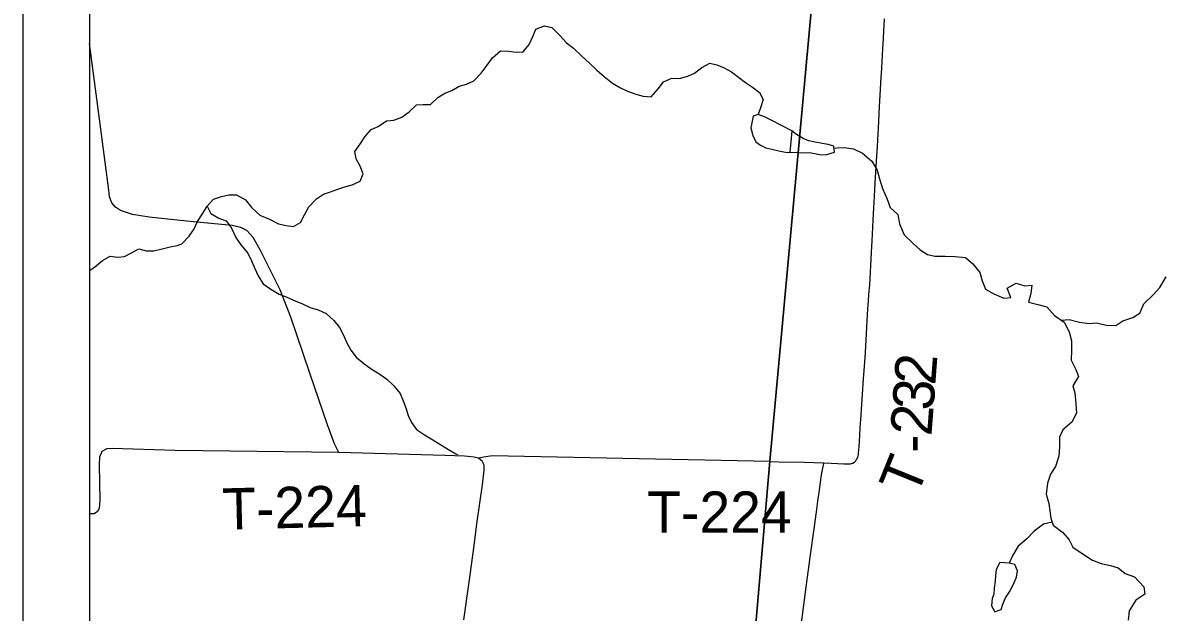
# Model space of a CAD drawing. Extents: x 0 to 34, y 0 to 22.
# Drawn here: x 2.17 to 3.738, y 15.952 to 16.763 of the extents above; entities that cross this region are included whole.
import ezdxf

# ---------------------------------------------------------------- set-up
doc = ezdxf.new("R2010")
doc.units = 0
for name, color, linetype in [('Default', 7, 'Continuous'), ('GM_X_County_Road', 7, 'Continuous'), ('GM_X_Minor_Lake', 7, 'Continuous'), ('GM_X_Minor_River', 7, 'Continuous'), ('GM_X_Township_Road', 7, 'Continuous'), ('GM_X_Township_Road_Text', 7, 'Continuous'), ('SH_Cut_Line', 7, 'Continuous'), ('SH_Data', 7, 'Continuous')]:
    doc.layers.add(name, color=color, linetype=linetype)

msp = doc.modelspace()

# ---------------------------------------------------------------- linework, layer by layer
at = {"layer": 'Default'}
for points in [[(2.2621, 19.2337), (2.2621, 13.6252), (2.9696, 13.6252), (3.0429, 14.4692), (3.0457, 14.4958), (3.0617, 14.6751), (3.1343, 15.4291), (3.1974, 16.1596), (3.2667, 16.919), (3.2768, 17.1355), (3.47, 19.2407)], [(3.47, 19.2407), (3.2768, 17.1355), (3.2667, 16.919), (3.1974, 16.1596), (3.1343, 15.4291), (3.1796, 15.4266), (4.2078, 15.3826), (4.2393, 15.3805), (4.819, 15.349), (5.5157, 15.319), (7.9465, 15.1727), (8.1234, 15.1688), (8.137, 15.3372), (8.146, 15.4642), (8.2031, 16.209), (8.2895, 16.85), (8.3286, 17.3076), (8.3307, 17.3314), (8.3334, 17.361), (8.3935, 18.0719)]]:
    msp.add_lwpolyline(points, dxfattribs=at)
at = {"layer": 'GM_X_County_Road'}
for points in [[(2.6049, 16.1715), (2.5987, 16.1832), (2.5893, 16.2095), (2.5651, 16.2807), (2.5388, 16.3579), (2.5242, 16.3953), (2.4965, 16.4504), (2.4872, 16.4673), (2.4785, 16.477), (2.47, 16.481), (2.4584, 16.4836), (2.3954, 16.4896), (2.3441, 16.4954), (2.3214, 16.4988), (2.3047, 16.5043), (2.2976, 16.509), (2.2928, 16.515), (2.2898, 16.5232), (2.2885, 16.5326), (2.2786, 16.6093), (2.268, 16.6892), (2.2621, 16.7341)], [(2.7969, 16.1635), (2.7907, 16.1653), (2.7774, 16.1665), (2.7506, 16.1673), (2.6049, 16.1715)], [(2.7767, 15.9414), (2.7837, 15.9931), (2.7897, 16.0368), (2.795, 16.0765), (2.8022, 16.1271), (2.8046, 16.1471), (2.8044, 16.1542), (2.8017, 16.1598), (2.7969, 16.1635)]]:
    msp.add_lwpolyline(points, dxfattribs=at)
at = {"layer": 'GM_X_Minor_Lake'}
msp.add_line((3.2275, 16.614), (3.2247, 16.5843), dxfattribs=at)
for points in [[(3.2275, 16.614), (3.199, 16.6287), (3.19, 16.6334), (3.181, 16.6366), (3.1745, 16.6341), (3.1711, 16.6182), (3.1739, 16.6076), (3.1779, 16.5991), (3.1842, 16.5941), (3.1918, 16.5905), (3.2001, 16.5888), (3.2095, 16.5863), (3.2185, 16.5846), (3.2247, 16.5843)], [(3.2247, 16.5843), (3.2318, 16.5848), (3.2424, 16.5838), (3.2519, 16.5844), (3.2677, 16.581), (3.2757, 16.5816), (3.286, 16.5848), (3.285, 16.5928), (3.2775, 16.5952), (3.2692, 16.5965), (3.2593, 16.5983), (3.251, 16.6003), (3.2432, 16.6035), (3.2339, 16.6091), (3.2275, 16.614)], [(3.5263, 16.0194), (3.5134, 16.02), (3.5083, 16.0106), (3.5074, 16.0016), (3.5068, 15.9951), (3.5055, 15.9849), (3.505, 15.9766), (3.5029, 15.9705), (3.502, 15.9607), (3.5063, 15.9523), (3.511, 15.954)], [(3.511, 15.954), (3.5151, 15.9555), (3.5176, 15.963), (3.5211, 15.9717), (3.5266, 15.9799), (3.5321, 15.9904), (3.5361, 16.0002), (3.5374, 16.0089), (3.5338, 16.0173), (3.5263, 16.0194)]]:
    msp.add_lwpolyline(points, dxfattribs=at)
at = {"layer": 'GM_X_Minor_River'}
for points in [[(2.3892, 16.4587), (2.3993, 16.4691), (2.406, 16.4792), (2.4107, 16.4893), (2.4174, 16.4998), (2.4237, 16.5103), (2.4326, 16.52), (2.4433, 16.5239), (2.4536, 16.526), (2.4642, 16.5261), (2.4765, 16.5191), (2.4854, 16.5083), (2.4962, 16.4982), (2.5093, 16.4926), (2.5217, 16.4863), (2.5326, 16.4838), (2.5424, 16.4824), (2.552, 16.4879), (2.5576, 16.4984), (2.5635, 16.5097), (2.5739, 16.5205), (2.5839, 16.5267), (2.5934, 16.5303), (2.6034, 16.5339), (2.6129, 16.5368), (2.6232, 16.5396), (2.6339, 16.545), (2.6383, 16.5548), (2.6339, 16.5655), (2.6285, 16.5755), (2.6268, 16.5854), (2.6338, 16.5951), (2.6405, 16.6056), (2.6494, 16.6157), (2.6589, 16.62), (2.6701, 16.6278), (2.6803, 16.6287), (2.6914, 16.633), (2.7014, 16.64), (2.7114, 16.6497), (2.7209, 16.6502), (2.7308, 16.6504), (2.7408, 16.6597), (2.7504, 16.6659), (2.7603, 16.6695), (2.7703, 16.6754), (2.7802, 16.6782), (2.7902, 16.683), (2.8006, 16.6934), (2.8088, 16.7046), (2.8162, 16.7143), (2.827, 16.7239), (2.838, 16.7237), (2.8486, 16.7223), (2.858, 16.7225), (2.8666, 16.733), (2.8714, 16.7439), (2.8757, 16.754), (2.8876, 16.7583), (2.8974, 16.7562), (2.9085, 16.7454), (2.9178, 16.7353), (2.9275, 16.7276), (2.939, 16.7167), (2.9494, 16.707), (2.9594, 16.6973), (2.9695, 16.6888), (2.9811, 16.6798), (2.9919, 16.6731), (3.0017, 16.6688), (3.0129, 16.6647), (3.0231, 16.6619), (3.0341, 16.6609), (3.0438, 16.6717), (3.0508, 16.6814), (3.0623, 16.6865), (3.0732, 16.6859), (3.0843, 16.6894), (3.0938, 16.6934), (3.1039, 16.7012), (3.1146, 16.707), (3.1244, 16.7049), (3.1345, 16.7009), (3.1443, 16.695), (3.154, 16.688), (3.1637, 16.6806), (3.1734, 16.6743), (3.1831, 16.6669), (3.1882, 16.6573), (3.1846, 16.6472), (3.181, 16.6366)], [(3.2853, 16.5901), (3.2895, 16.5905), (3.2993, 16.591), (3.3122, 16.5892), (3.3246, 16.5833), (3.3372, 16.5721), (3.3445, 16.5598), (3.3481, 16.5479), (3.352, 16.5346), (3.3585, 16.52), (3.3628, 16.5086), (3.3732, 16.4989), (3.3756, 16.4859), (3.3817, 16.471), (3.394, 16.459), (3.4037, 16.4505), (3.4138, 16.4438), (3.4239, 16.4414), (3.438, 16.4415), (3.452, 16.4412), (3.466, 16.4398), (3.4764, 16.4312), (3.4856, 16.4193), (3.4892, 16.4078), (3.4935, 16.3964), (3.5051, 16.3897), (3.5186, 16.3837), (3.5285, 16.3847), (3.5234, 16.3977), (3.5357, 16.4046), (3.5478, 16.401), (3.5572, 16.4016), (3.5559, 16.3902), (3.5526, 16.3785), (3.5654, 16.3752), (3.5778, 16.3719), (3.5886, 16.36), (3.6017, 16.3506), (3.6086, 16.3376), (3.6117, 16.325), (3.6119, 16.3125), (3.6112, 16.2984), (3.6178, 16.2858), (3.6213, 16.2762), (3.6135, 16.2631), (3.6163, 16.2536), (3.6179, 16.2387), (3.6188, 16.2258), (3.6121, 16.2134), (3.6001, 16.2027), (3.5954, 16.1925), (3.5951, 16.1796), (3.5945, 16.1664), (3.5896, 16.1521), (3.583, 16.1416), (3.5789, 16.1295), (3.5771, 16.1144), (3.5806, 16.1014), (3.5819, 16.0911), (3.5832, 16.0812), (3.5865, 16.0717), (3.5999, 16.0616), (3.6088, 16.0515), (3.6135, 16.0412), (3.6277, 16.0318), (3.6408, 16.0236), (3.6524, 16.0188), (3.6656, 16.0159), (3.6758, 16.013), (3.6855, 16.0052), (3.6983, 16.0004), (3.7112, 15.9865), (3.7126, 15.9766), (3.7003, 15.9682), (3.6909, 15.9535), (3.6895, 15.9407)], [(2.4237, 16.5103), (2.4288, 16.5003), (2.44, 16.494), (2.4498, 16.49), (2.4572, 16.48), (2.4633, 16.4674), (2.4699, 16.457), (2.4796, 16.4458), (2.4847, 16.4354), (2.4894, 16.4247), (2.4941, 16.4144), (2.5007, 16.4036), (2.5111, 16.3962), (2.5227, 16.3895), (2.5325, 16.3855), (2.5423, 16.3812), (2.5547, 16.376), (2.5655, 16.3708), (2.5765, 16.3679), (2.5873, 16.3628), (2.5978, 16.3531), (2.6059, 16.3434), (2.6114, 16.3327), (2.6157, 16.3224), (2.6212, 16.3124), (2.6285, 16.3028), (2.6393, 16.2938), (2.6494, 16.2868), (2.661, 16.2793), (2.6707, 16.2723), (2.6804, 16.263), (2.6889, 16.2526), (2.6932, 16.2426), (2.6968, 16.2331), (2.7, 16.2224), (2.7047, 16.2128), (2.7117, 16.2032), (2.7226, 16.1958), (2.7342, 16.1887), (2.7458, 16.1816), (2.7555, 16.1754), (2.7656, 16.1695), (2.7682, 16.1687)], [(2.2621, 16.4221), (2.2691, 16.4264), (2.2799, 16.4357), (2.2906, 16.4416), (2.3005, 16.4404), (2.31, 16.441), (2.3199, 16.4461), (2.3299, 16.4516), (2.3401, 16.4488), (2.3507, 16.449), (2.3618, 16.4515), (2.3728, 16.4544), (2.3827, 16.4565), (2.3892, 16.4587)], [(3.5974, 16.3537), (3.6086, 16.3543), (3.6229, 16.3509), (3.6361, 16.3492), (3.6463, 16.3501), (3.6595, 16.3468), (3.6728, 16.3462), (3.6824, 16.3528), (3.6961, 16.3571), (3.7057, 16.3633), (3.7113, 16.3761), (3.7244, 16.3888), (3.7333, 16.3984), (3.742, 16.4131)], [(3.5851, 16.0756), (3.5732, 16.0731), (3.5605, 16.0631), (3.5505, 16.0527), (3.5385, 16.0427), (3.5311, 16.0303), (3.5263, 16.0194)]]:
    msp.add_lwpolyline(points, dxfattribs=at)
at = {"layer": 'GM_X_Township_Road'}
for points in [[(3.2715, 16.1572), (3.2814, 16.1569), (3.2988, 16.156), (3.3034, 16.1559), (3.3068, 16.156), (3.3082, 16.1561), (3.3093, 16.1563), (3.3105, 16.1566), (3.3115, 16.157), (3.3124, 16.1574), (3.3138, 16.1585), (3.3154, 16.1602), (3.3165, 16.1618), (3.3175, 16.1635), (3.3182, 16.1652), (3.3186, 16.1669), (3.3189, 16.1687), (3.3192, 16.1709), (3.3195, 16.1748), (3.3198, 16.1803), (3.3202, 16.1863), (3.3214, 16.2049), (3.3227, 16.2234), (3.3247, 16.2517), (3.3261, 16.2727), (3.3277, 16.2958), (3.3286, 16.3092), (3.3296, 16.3265), (3.3308, 16.3527), (3.3313, 16.361), (3.3318, 16.3692), (3.3326, 16.3795), (3.3334, 16.3893), (3.3344, 16.4023), (3.335, 16.411), (3.3355, 16.4195), (3.3361, 16.4286), (3.337, 16.4465), (3.3383, 16.4715), (3.3392, 16.4915), (3.34, 16.5075), (3.3409, 16.524), (3.3418, 16.5419), (3.3432, 16.5651), (3.345, 16.5931), (3.3465, 16.6175), (3.348, 16.6475), (3.3488, 16.6631), (3.3502, 16.6873), (3.351, 16.6996), (3.3526, 16.7273), (3.353, 16.7334), (3.355, 16.7681)], [(2.6049, 16.1715), (2.3798, 16.1743), (2.2932, 16.1771), (2.2859, 16.1764), (2.2791, 16.1731), (2.2759, 16.1653), (2.2756, 16.1551), (2.2761, 16.1054), (2.2753, 16.0943), (2.273, 16.0902), (2.2687, 16.0873), (2.2621, 16.0869)], [(2.7969, 16.1635), (2.7907, 16.1653), (2.7774, 16.1665), (2.7506, 16.1673), (2.6049, 16.1715)], [(3.1976, 16.1591), (2.8374, 16.1666), (2.8159, 16.1671), (2.8066, 16.1656), (2.7969, 16.1635)], [(3.1976, 16.1591), (3.2098, 16.1588), (3.2448, 16.1581), (3.2581, 16.1576), (3.2698, 16.1573), (3.2715, 16.1572)], [(3.2371, 15.9088), (3.2434, 15.9584), (3.2477, 15.9897), (3.2514, 16.017), (3.2532, 16.0307), (3.258, 16.0664), (3.2612, 16.0897), (3.2633, 16.1044), (3.2649, 16.1165), (3.2669, 16.1306), (3.2684, 16.1406), (3.2701, 16.1499), (3.2714, 16.1565), (3.2715, 16.1572)]]:
    msp.add_lwpolyline(points, dxfattribs=at)
at = {"layer": 'SH_Cut_Line'}
for points in [[(3.5682, 20.4252), (2.2621, 20.4252), (2.2621, 13.6252), (2.9696, 13.6252), (3.0429, 14.4692), (3.0457, 14.4958), (3.0617, 14.6751), (3.1343, 15.4291), (3.1974, 16.1596), (3.2667, 16.919), (3.2768, 17.1355), (3.47, 19.2407), (3.4748, 19.2963), (3.4903, 19.4759), (3.4966, 19.5464), (3.5066, 19.6647), (3.5092, 19.6961), (3.5125, 19.7343), (3.5169, 19.7823), (3.5231, 19.8516), (3.5424, 20.1754)], [(2.9696, 13.6252), (9.0621, 13.6252), (9.0621, 20.4252), (3.5682, 20.4252), (3.5424, 20.1754), (3.5231, 19.8516), (3.5169, 19.7823), (3.5125, 19.7343), (3.5092, 19.6961), (3.5066, 19.6647), (3.4966, 19.5464), (3.4903, 19.4759), (3.4748, 19.2963), (3.47, 19.2407), (3.2768, 17.1355), (3.2667, 16.919), (3.1974, 16.1596), (3.1343, 15.4291), (3.0617, 14.6751), (3.0457, 14.4958), (3.0429, 14.4692)]]:
    msp.add_lwpolyline(points, close=True, dxfattribs=at)
at = {"layer": 'SH_Data'}
msp.add_line((2.1704, 20.5628), (2.1704, 13.5628), dxfattribs=at)

# ---------------------------------------------------------------- texts
at = {"layer": 'GM_X_Township_Road_Text'}
for s, height, rotation, p in [('2', 0.0568, 85.7428, (3.4245, 16.2632)), ('3', 0.0568, 85.7152, (3.4219, 16.2283)), ('2', 0.0568, 85.6141, (3.4192, 16.1933)), ('-', 0.0568, 89.8532, (3.4192, 16.171)), ('T', 0.0568, 67.8727, (3.3987, 16.1085)), ('T-224', 0.05682, 1.4032, (2.4453, 16.0653)), ('T-224', 0.05682, 0, (3.0287, 16.0611))]:
    msp.add_text(s, height=height, rotation=rotation, dxfattribs=at).set_placement(p)

doc.saveas('drawing.dxf')
